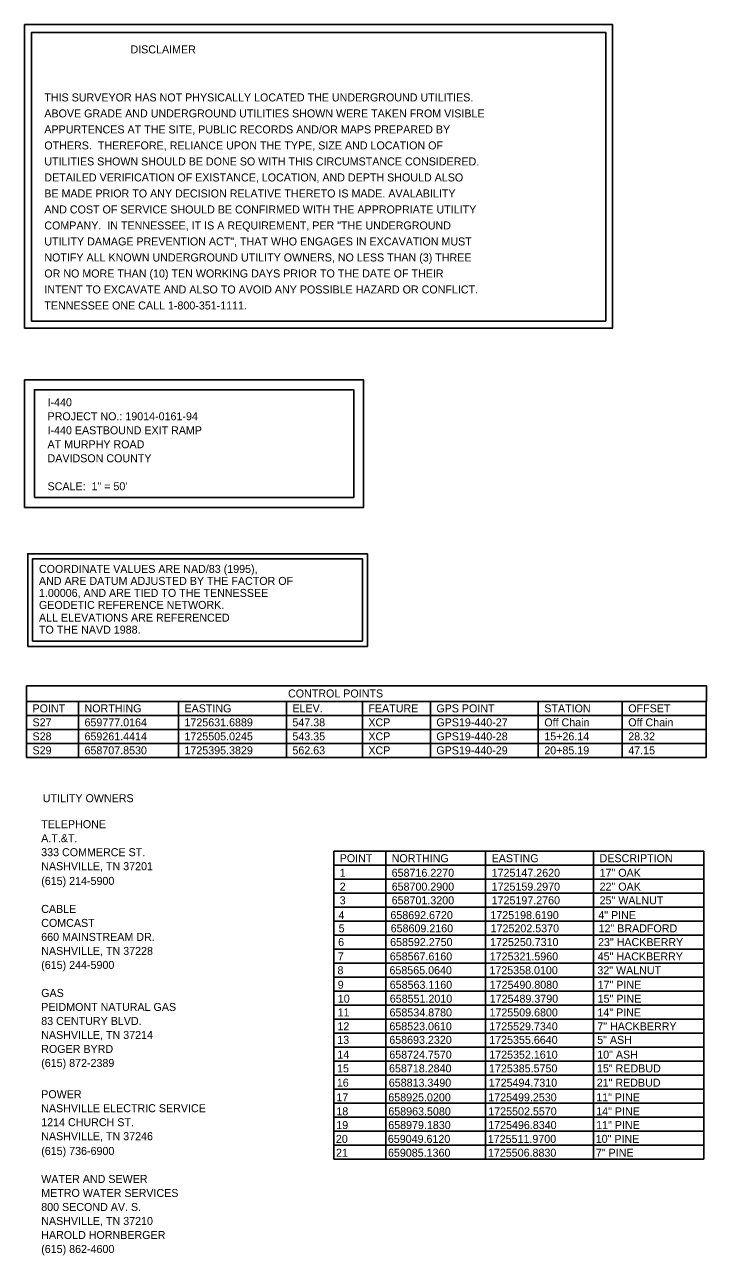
# Model space of a CAD drawing. Extents: x 1724534 to 1727318, y 657156 to 660047.
# Drawn here: x 1726443 to 1726870, y 658429 to 659198 of the extents above; entities that cross this region are included whole.
import ezdxf

# ---------------------------------------------------------------- set-up
doc = ezdxf.new("R2010")
doc.units = 0
for name, color, linetype in [('SURVEY - CONTROL with Text', 7, 'Continuous'), ('SURVEY - PROJECT INFORMATION and NOTES', 7, 'Continuous'), ('SURVEY - UTILITIES - Owners', 7, 'Continuous'), ('SURVEY - VEGETATION - Features with Text', 7, 'Continuous')]:
    doc.layers.add(name, color=color, linetype=linetype)

msp = doc.modelspace()

# ---------------------------------------------------------------- linework, layer by layer
at = {"layer": 'SURVEY - CONTROL with Text'}
for p, q in [((1726444.66, 658775.58), (1726869.66, 658775.58)), ((1726444.66, 658775.58), (1726444.66, 658740.58)), ((1726477.16, 658775.58), (1726477.16, 658740.58)), ((1726539.66, 658775.58), (1726539.66, 658740.58)), ((1726607.16, 658775.58), (1726607.16, 658740.58)), ((1726654.66, 658775.58), (1726654.66, 658740.58)), ((1726697.16, 658775.58), (1726697.16, 658740.58)), ((1726764.66, 658775.58), (1726764.66, 658740.58)), ((1726817.16, 658775.58), (1726817.16, 658740.58)), ((1726869.66, 658775.58), (1726869.66, 658740.58)), ((1726444.66, 658766.83), (1726869.66, 658766.83)), ((1726444.66, 658758.08), (1726869.66, 658758.08)), ((1726444.66, 658758.08), (1726869.66, 658758.08)), ((1726444.66, 658758.08), (1726869.66, 658758.08)), ((1726444.66, 658758.08), (1726869.66, 658758.08)), ((1726444.66, 658758.08), (1726869.66, 658758.08)), ((1726444.66, 658758.08), (1726869.66, 658758.08)), ((1726444.66, 658758.08), (1726869.66, 658758.08)), ((1726444.66, 658758.08), (1726869.66, 658758.08)), ((1726444.66, 658749.33), (1726869.66, 658749.33)), ((1726444.66, 658749.33), (1726869.66, 658749.33)), ((1726444.66, 658749.33), (1726869.66, 658749.33)), ((1726444.66, 658749.33), (1726869.66, 658749.33)), ((1726444.66, 658749.33), (1726869.66, 658749.33)), ((1726444.66, 658749.33), (1726869.66, 658749.33)), ((1726444.66, 658749.33), (1726869.66, 658749.33)), ((1726444.66, 658749.33), (1726869.66, 658749.33)), ((1726444.66, 658740.58), (1726869.66, 658740.58)), ((1726444.66, 658740.58), (1726869.66, 658740.58)), ((1726444.66, 658740.58), (1726869.66, 658740.58)), ((1726444.66, 658740.58), (1726869.66, 658740.58)), ((1726444.66, 658740.58), (1726869.66, 658740.58)), ((1726444.66, 658740.58), (1726869.66, 658740.58)), ((1726444.66, 658740.58), (1726869.66, 658740.58)), ((1726444.66, 658740.58), (1726869.66, 658740.58))]:
    msp.add_line(p, q, dxfattribs=at)
for points in [[(1726445.39, 658809.83), (1726445.39, 658867.77), (1726657.8, 658867.77), (1726657.8, 658809.83)], [(1726448.47, 658813.19), (1726448.47, 658864.69), (1726654.73, 658864.69), (1726654.73, 658813.19)], [(1726444.66, 658775.58), (1726869.77, 658775.58), (1726869.77, 658785.3), (1726444.66, 658785.3)]]:
    msp.add_lwpolyline(points, close=True, dxfattribs=at)
at = {"layer": 'SURVEY - PROJECT INFORMATION and NOTES'}
for points in [[(1726443.45, 658896.79), (1726443.45, 658976.37), (1726655.39, 658976.37), (1726655.39, 658896.79)], [(1726449.55, 658902.88), (1726449.55, 658970.27), (1726649.29, 658970.27), (1726649.29, 658902.88)]]:
    msp.add_lwpolyline(points, close=True, dxfattribs=at)
at = {"layer": 'SURVEY - UTILITIES - Owners'}
for points in [[(1726443.48, 659008.77), (1726443.48, 659198.41), (1726811.15, 659198.41), (1726811.15, 659008.77)], [(1726447.83, 659013.12), (1726447.83, 659193.57), (1726806.8, 659193.57), (1726806.8, 659013.12)]]:
    msp.add_lwpolyline(points, close=True, dxfattribs=at)
at = {"layer": 'SURVEY - VEGETATION - Features with Text'}
for p, q in [((1726636.73, 658681.93), (1726868.13, 658681.93)), ((1726636.73, 658681.93), (1726636.73, 658489.43)), ((1726669.23, 658681.93), (1726669.23, 658489.43)), ((1726731.73, 658681.93), (1726731.73, 658489.43)), ((1726799.23, 658681.93), (1726799.23, 658489.43)), ((1726868.13, 658681.93), (1726868.13, 658489.43)), ((1726636.73, 658673.18), (1726868.13, 658673.18)), ((1726636.73, 658664.43), (1726861.73, 658664.43)), ((1726636.73, 658664.43), (1726861.73, 658664.43)), ((1726636.73, 658664.43), (1726861.73, 658664.43)), ((1726636.73, 658664.43), (1726868.13, 658664.43)), ((1726636.73, 658655.68), (1726861.73, 658655.68)), ((1726636.73, 658655.68), (1726861.73, 658655.68)), ((1726636.73, 658655.68), (1726861.73, 658655.68)), ((1726636.73, 658655.68), (1726868.13, 658655.68)), ((1726636.73, 658646.93), (1726861.73, 658646.93)), ((1726636.73, 658646.93), (1726861.73, 658646.93)), ((1726636.73, 658646.93), (1726861.73, 658646.93)), ((1726636.73, 658646.93), (1726868.13, 658646.93)), ((1726636.73, 658638.18), (1726861.73, 658638.18)), ((1726636.73, 658638.18), (1726861.73, 658638.18)), ((1726636.73, 658638.18), (1726861.73, 658638.18)), ((1726636.73, 658638.18), (1726868.13, 658638.18)), ((1726636.73, 658629.43), (1726861.73, 658629.43)), ((1726636.73, 658629.43), (1726861.73, 658629.43)), ((1726636.73, 658629.43), (1726861.73, 658629.43)), ((1726636.73, 658629.43), (1726868.13, 658629.43)), ((1726636.73, 658620.68), (1726868.13, 658620.68)), ((1726636.73, 658611.93), (1726868.13, 658611.93)), ((1726636.73, 658603.18), (1726868.13, 658603.18)), ((1726636.73, 658594.43), (1726868.13, 658594.43)), ((1726636.73, 658585.68), (1726868.13, 658585.68)), ((1726636.73, 658576.93), (1726868.13, 658576.93)), ((1726636.73, 658568.18), (1726868.13, 658568.18)), ((1726636.73, 658559.43), (1726868.13, 658559.43)), ((1726636.73, 658550.68), (1726868.13, 658550.68)), ((1726636.73, 658541.93), (1726868.13, 658541.93)), ((1726636.73, 658533.18), (1726868.13, 658533.18)), ((1726636.73, 658524.43), (1726868.13, 658524.43)), ((1726636.73, 658515.68), (1726868.13, 658515.68)), ((1726636.73, 658506.93), (1726868.13, 658506.93)), ((1726636.73, 658498.18), (1726868.13, 658498.18)), ((1726636.73, 658489.43), (1726868.13, 658489.43))]:
    msp.add_line(p, q, dxfattribs=at)

# ---------------------------------------------------------------- texts
at = {"layer": 'SURVEY - CONTROL with Text'}
for s, height, p in [('COORDINATE VALUES ARE NAD/83 (1995),', 4.998, (1726452.43, 658855.82)), ('AND ARE DATUM ADJUSTED BY THE FACTOR OF', 4.998, (1726452.43, 658848.32)), ('1.00006, AND ARE TIED TO THE TENNESSEE', 4.998, (1726452.43, 658840.82)), ('GEODETIC REFERENCE NETWORK.', 4.998, (1726452.43, 658833.32)), ('ALL ELEVATIONS ARE REFERENCED', 4.998, (1726452.43, 658825.36)), ('TO THE NAVD 1988.', 4.998, (1726452.43, 658817.86)), ('CONTROL POINTS', 5, (1726608.17, 658778)), ('POINT', 5, (1726448.41, 658768.7)), ('NORTHING', 5, (1726480.91, 658768.7)), ('EASTING', 5, (1726543.41, 658768.7)), ('ELEV.', 5, (1726610.91, 658768.7)), ('FEATURE', 5, (1726658.41, 658768.7)), ('GPS POINT', 5, (1726700.91, 658768.7)), ('STATION', 5, (1726768.41, 658768.7)), ('OFFSET', 5, (1726820.91, 658768.7)), ('S27', 5, (1726448.41, 658759.95)), ('659777.0164', 5, (1726480.91, 658759.95)), ('1725631.6889', 5, (1726543.41, 658759.95)), ('547.38', 5, (1726610.91, 658759.95)), ('XCP', 5, (1726658.41, 658759.95)), ('GPS19-440-27', 5, (1726700.91, 658759.95)), ('Off Chain', 5, (1726768.41, 658759.95)), ('Off Chain', 5, (1726820.91, 658759.95)), ('S28', 5, (1726448.41, 658751.2)), ('659261.4414', 5, (1726480.91, 658751.2)), ('1725505.0245', 5, (1726543.41, 658751.2)), ('543.35', 5, (1726610.91, 658751.2)), ('XCP', 5, (1726658.41, 658751.2)), ('GPS19-440-28', 5, (1726700.91, 658751.2)), ('15+26.14', 5, (1726768.41, 658751.2)), ('28.32', 5, (1726820.91, 658751.2)), ('S29', 5, (1726448.41, 658742.45)), ('658707.8530', 5, (1726480.91, 658742.45)), ('1725395.3829', 5, (1726543.41, 658742.45)), ('562.63', 5, (1726610.91, 658742.45)), ('XCP', 5, (1726658.41, 658742.45)), ('GPS19-440-29', 5, (1726700.91, 658742.45)), ('20+85.19', 5, (1726768.41, 658742.45)), ('47.15', 5, (1726820.91, 658742.45))]:
    msp.add_text(s, height=height, dxfattribs=at).set_placement(p)
at = {"layer": 'SURVEY - PROJECT INFORMATION and NOTES'}
for s, p in [('I-440', (1726457.81, 658959.94)), ('PROJECT NO.: 19014-0161-94', (1726457.81, 658951.19)), ('I-440 EASTBOUND EXIT RAMP', (1726457.81, 658942.44)), ('AT MURPHY ROAD', (1726457.81, 658933.7)), ('DAVIDSON COUNTY', (1726457.81, 658924.95)), ('SCALE:  1" = 50\'', (1726457.81, 658907.45))]:
    msp.add_text(s, height=4.998, dxfattribs=at).set_placement(p)
at = {"layer": 'SURVEY - UTILITIES - Owners'}
for s, p in [('                             DISCLAIMER', (1726455.79, 659180.42)), ('THIS SURVEYOR HAS NOT PHYSICALLY LOCATED THE UNDERGROUND UTILITIES.', (1726455.79, 659150.42)), ('ABOVE GRADE AND UNDERGROUND UTILITIES SHOWN WERE TAKEN FROM VISIBLE', (1726455.79, 659140.42)), ('APPURTENCES AT THE SITE, PUBLIC RECORDS AND/OR MAPS PREPARED BY', (1726455.79, 659130.42)), ('OTHERS.  THEREFORE, RELIANCE UPON THE TYPE, SIZE AND LOCATION OF', (1726455.79, 659120.42)), ('UTILITIES SHOWN SHOULD BE DONE SO WITH THIS CIRCUMSTANCE CONSIDERED.', (1726455.79, 659110.42)), ('DETAILED VERIFICATION OF EXISTANCE, LOCATION, AND DEPTH SHOULD ALSO', (1726455.79, 659100.42)), ('BE MADE PRIOR TO ANY DECISION RELATIVE THERETO IS MADE. AVALABILITY', (1726455.79, 659090.42)), ('AND COST OF SERVICE SHOULD BE CONFIRMED WITH THE APPROPRIATE UTILITY', (1726455.79, 659080.42)), ('COMPANY.  IN TENNESSEE, IT IS A REQUIREMENT, PER "THE UNDERGROUND', (1726455.79, 659070.42)), ('UTILITY DAMAGE PREVENTION ACT", THAT WHO ENGAGES IN EXCAVATION MUST', (1726455.79, 659060.42)), ('NOTIFY ALL KNOWN UNDERGROUND UTILITY OWNERS, NO LESS THAN (3) THREE', (1726455.79, 659050.42)), ('OR NO MORE THAN (10) TEN WORKING DAYS PRIOR TO THE DATE OF THEIR', (1726455.79, 659040.42)), ('INTENT TO EXCAVATE AND ALSO TO AVOID ANY POSSIBLE HAZARD OR CONFLICT.', (1726455.79, 659030.42)), ('TENNESSEE ONE CALL 1-800-351-1111.', (1726455.79, 659020.42)), ('UTILITY OWNERS', (1726454.8, 658712.57)), ('TELEPHONE', (1726453.85, 658696.33)), ('A.T.&T.', (1726453.85, 658687.58)), ('333 COMMERCE ST.', (1726453.85, 658678.83)), ('NASHVILLE, TN 37201', (1726453.85, 658670.08)), ('(615) 214-5900', (1726453.85, 658660.88)), ('CABLE', (1726453.85, 658643.38)), ('COMCAST', (1726453.85, 658634.63)), ('660 MAINSTREAM DR.', (1726453.85, 658625.88)), ('NASHVILLE, TN 37228', (1726453.85, 658617.13)), ('(615) 244-5900', (1726453.85, 658608.38)), ('GAS', (1726453.85, 658590.88)), ('PEIDMONT NATURAL GAS', (1726453.85, 658582.13)), ('83 CENTURY BLVD.', (1726453.85, 658573.38)), ('NASHVILLE, TN 37214', (1726453.85, 658564.63)), ('ROGER BYRD', (1726453.85, 658555.88)), ('(615) 872-2389', (1726453.85, 658547.13)), ('POWER', (1726453.85, 658527.61)), ('NASHVILLE ELECTRIC SERVICE', (1726453.85, 658518.86)), ('1214 CHURCH ST.', (1726453.85, 658510.11)), ('NASHVILLE, TN 37246', (1726453.85, 658501.36)), ('(615) 736-6900', (1726453.85, 658492.15)), ('WATER AND SEWER', (1726453.85, 658474.65)), ('METRO WATER SERVICES', (1726453.85, 658465.9)), ('800 SECOND AV. S.', (1726453.85, 658457.15)), ('NASHVILLE, TN 37210', (1726453.85, 658448.4)), ('HAROLD HORNBERGER', (1726453.85, 658439.65)), ('(615) 862-4600', (1726453.85, 658430.9))]:
    msp.add_text(s, height=5, dxfattribs=at).set_placement(p)
at = {"layer": 'SURVEY - VEGETATION - Features with Text'}
for s, p in [('POINT', (1726640.48, 658675.06)), ('NORTHING', (1726672.98, 658675.06)), ('EASTING', (1726735.48, 658675.06)), ('DESCRIPTION', (1726802.98, 658675.06)), ('1', (1726640.48, 658665.96)), ('658716.2270', (1726672.98, 658665.96)), ('1725147.2620', (1726735.48, 658665.96)), ('17" OAK', (1726802.98, 658665.96)), ('2', (1726640.48, 658657.31)), ('658700.2900', (1726672.98, 658657.31)), ('1725159.2970', (1726735.48, 658657.31)), ('22" OAK', (1726802.98, 658657.31)), ('3', (1726640.48, 658648.75)), ('658701.3200', (1726672.98, 658648.75)), ('1725197.2760', (1726735.48, 658648.75)), ('25" WALNUT', (1726802.98, 658648.75)), ('4', (1726639.69, 658639.52)), ('658692.6720', (1726672.19, 658639.52)), ('1725198.6190', (1726734.69, 658639.52)), ('4" PINE', (1726802.19, 658639.52)), ('5', (1726639.85, 658631.26)), ('658609.2160', (1726672.35, 658631.26)), ('1725202.5370', (1726734.85, 658631.26)), ('12" BRADFORD', (1726802.35, 658631.26)), ('6', (1726639.51, 658622.67)), ('658592.2750', (1726672.01, 658622.67)), ('1725250.7310', (1726734.51, 658622.67)), ('23" HACKBERRY', (1726802.01, 658622.67)), ('7', (1726639.3, 658613.72)), ('658567.6160', (1726671.8, 658613.72)), ('1725321.5960', (1726734.3, 658613.72)), ('45" HACKBERRY', (1726801.8, 658613.72)), ('8', (1726639.1, 658605.05)), ('658565.0640', (1726671.6, 658605.05)), ('1725358.0100', (1726734.1, 658605.05)), ('32" WALNUT', (1726801.6, 658605.05)), ('9', (1726639.26, 658595.99)), ('658563.1160', (1726671.76, 658595.99)), ('1725490.8080', (1726734.26, 658595.99)), ('17" PINE', (1726801.76, 658595.99)), ('10', (1726639.29, 658587.3)), ('658551.2010', (1726671.79, 658587.3)), ('1725489.3790', (1726734.29, 658587.3)), ('15" PINE', (1726801.79, 658587.3)), ('11', (1726639.14, 658578.71)), ('658534.8780', (1726671.64, 658578.71)), ('1725509.6800', (1726734.14, 658578.71)), ('14" PINE', (1726801.64, 658578.71)), ('12', (1726639.05, 658570.03)), ('658523.0610', (1726671.55, 658570.03)), ('1725529.7340', (1726734.05, 658570.03)), ('7" HACKBERRY', (1726801.55, 658570.03)), ('13', (1726638.99, 658561.57)), ('658693.2320', (1726671.49, 658561.57)), ('1725355.6640', (1726733.99, 658561.57)), ('5" ASH', (1726801.49, 658561.57)), ('14', (1726638.99, 658552.33)), ('658724.7570', (1726671.49, 658552.33)), ('1725352.1610', (1726733.99, 658552.33)), ('10" ASH', (1726801.49, 658552.33)), ('15', (1726638.83, 658543.74)), ('658718.2840', (1726671.33, 658543.74)), ('1725385.5750', (1726733.83, 658543.74)), ('15" REDBUD', (1726801.33, 658543.74)), ('16', (1726638.68, 658534.8)), ('658813.3490', (1726671.18, 658534.8)), ('1725494.7310', (1726733.68, 658534.8)), ('21" REDBUD', (1726801.18, 658534.8)), ('17', (1726638.39, 658525.66)), ('658925.0200', (1726670.89, 658525.66)), ('1725499.2530', (1726733.39, 658525.66)), ('11" PINE', (1726800.89, 658525.66)), ('18', (1726638.39, 658516.91)), ('658963.5080', (1726670.89, 658516.91)), ('1725502.5570', (1726733.39, 658516.91)), ('14" PINE', (1726800.89, 658516.91)), ('19', (1726638.34, 658508.34)), ('658979.1830', (1726670.84, 658508.34)), ('1725496.8340', (1726733.34, 658508.34)), ('11" PINE', (1726800.84, 658508.34)), ('20', (1726638.09, 658499.68)), ('659049.6120', (1726670.59, 658499.68)), ('1725511.9700', (1726733.09, 658499.68)), ('10" PINE', (1726800.59, 658499.68)), ('21', (1726638.17, 658491.05)), ('659085.1360', (1726670.67, 658491.05)), ('1725506.8830', (1726733.17, 658491.05)), ('7" PINE', (1726800.67, 658491.05))]:
    msp.add_text(s, height=5, dxfattribs=at).set_placement(p)

doc.saveas('drawing.dxf')
